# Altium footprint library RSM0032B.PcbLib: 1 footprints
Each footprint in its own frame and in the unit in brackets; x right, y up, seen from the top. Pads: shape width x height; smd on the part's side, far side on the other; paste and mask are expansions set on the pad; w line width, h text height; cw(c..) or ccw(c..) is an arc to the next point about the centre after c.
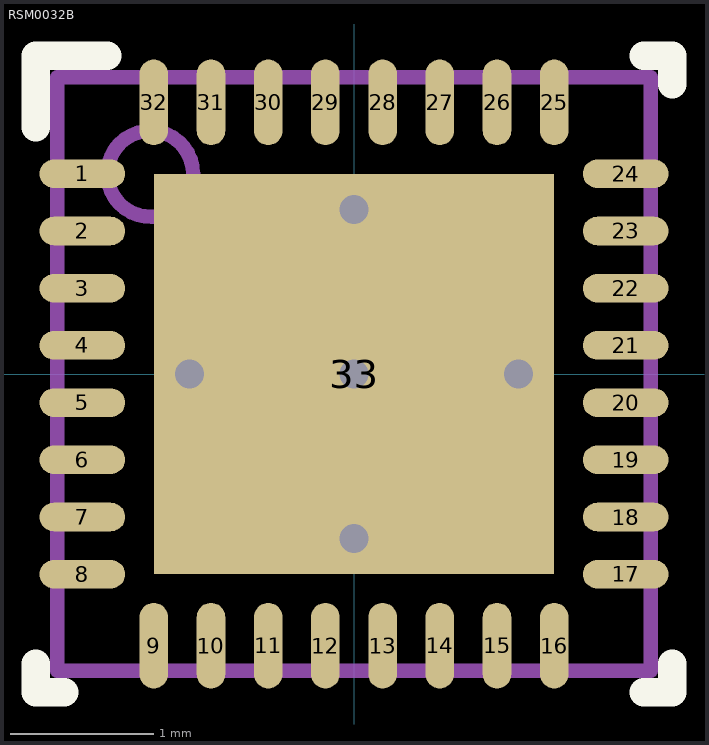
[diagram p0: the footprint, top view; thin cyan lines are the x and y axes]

## RSM0032B [mm] "QFN, 32-Leads, Body 4x4mm, Pitch 0.4mm, Thermal Pad 2.8x2.8mm, TI Recommended"
height 1
pads (33):
  oval 0.6x0.2 smd: 1(-1.9,1.4) 2(-1.9,1) 3(-1.9,0.6) 4(-1.9,0.2) 5(-1.9,-0.2) 6(-1.9,-0.6) 7(-1.9,-1) 8(-1.9,-1.4) 17(1.9,-1.4) 18(1.9,-1) 19(1.9,-0.6) 20(1.9,-0.2) 21(1.9,0.2) 22(1.9,0.6) 23(1.9,1) 24(1.9,1.4)
  oval 0.2x0.6 smd: 9(-1.4,-1.9) 10(-1,-1.9) 11(-0.6,-1.9) 12(-0.2,-1.9) 13(0.2,-1.9) 14(0.6,-1.9) 15(1,-1.9) 16(1.4,-1.9) 25(1.4,1.9) 26(1,1.9) 27(0.6,1.9) 28(0.2,1.9) 29(-0.2,1.9) 30(-0.6,1.9) 31(-1,1.9) 32(-1.4,1.9)
  rect 2.8x2.8 smd paste-1.4: 33(0,0)
via 0,1.15 diameter 0.5 hole 0.2
via -1.15,0 diameter 0.5 hole 0.2
via 0,0 diameter 0.5 hole 0.2
via 1.15,0 diameter 0.5 hole 0.2
via 0,-1.15 diameter 0.5 hole 0.2
Top Overlay:
  lines w0.2: -2.225,-2.025 -2.225,-2.225 -2.025,-2.225 ; -2.225,1.725 -2.225,2.225 -1.725,2.225 ; 2.025,-2.225 2.225,-2.225 2.225,-2.025 ; 2.025,2.225 2.225,2.225 2.225,2.025
Top Paste:
  region: -0.1,0.1 -0.1,1.329 -1.329,1.329 -1.329,0.1
  region: 1.329,0.1 1.329,1.329 0.1,1.329 0.1,0.1
  region: -0.1,-1.329 -0.1,-0.1 -1.329,-0.1 -1.329,-1.329
  region: 1.329,-1.329 1.329,-0.1 0.1,-0.1 0.1,-1.329
M5 Assembly Top:
  circle w0.1: c-1.425,1.4 r0.3
  lines w0.1: -2.075,-2.075 -2.075,2.075 2.075,2.075 2.075,-2.075 -2.075,-2.075
  text ".Designator" at -1.854,-0.508 h1.02
3D body: height 1, standoff 0, extent -2.075,-2.075 2.075,2.075
3D body: height 1.01, standoff 0.5, extent -1.73,1.095 -1.12,1.705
